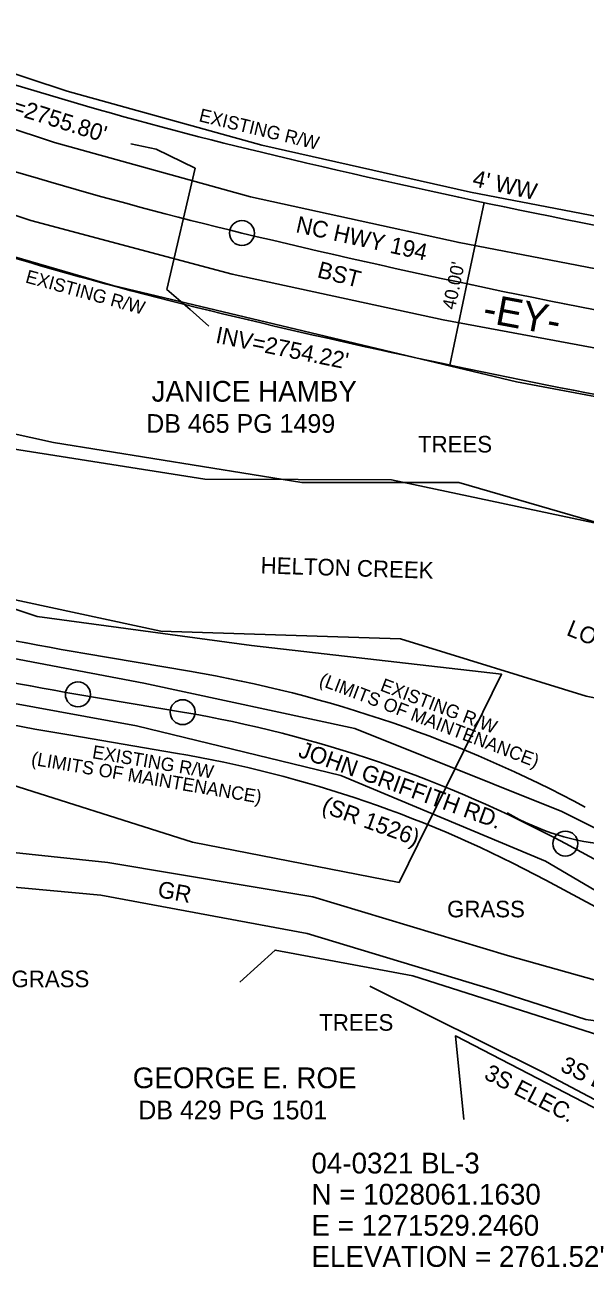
# Model space of a CAD drawing. Extents: x 1271070 to 1271913, y 1027587 to 1028435.
# Drawn here: x 1271367.8 to 1271502.6, y 1028008.8 to 1028308 of the extents above; entities that cross this region are included whole.
import ezdxf

# ---------------------------------------------------------------- set-up
doc = ezdxf.new("R2010")
doc.units = 0
for name, color, linetype in [('CTL Secondary Horizontal and Vertical Text', 7, 'Continuous'), ('Exist Horizontal Alignment', 7, 'Continuous'), ('Exist Horizontal Alignment Direction Label', 7, 'Continuous'), ('Exist Horizontal Alignment Point', 7, 'Continuous'), ('Exist Hydro Jurisdictional Stream or Body of Water', 7, 'Continuous'), ('Exist Hydro Jurisdictional Stream or Body of Water Text', 7, 'Continuous'), ('Exist Other Culture Fence Line', 7, 'Continuous'), ('Exist Other Culture Fence Line Text', 7, 'Continuous'), ('Exist Property Deed Book Text', 7, 'Continuous'), ('Exist Property Owner Text', 7, 'Continuous'), ('Exist Right of Way Line', 7, 'Continuous'), ('Exist Right of Way Line Text', 7, 'Continuous'), ('Exist Right of Way Width CELL', 7, 'Continuous'), ('Exist Roads EOP', 7, 'Continuous'), ('Exist Roads EOP Text', 7, 'Continuous'), ('Exist Roads Soil', 7, 'Continuous'), ('Exist Roads Soil Text', 7, 'Continuous'), ('Exist Structure Minor Pipes CMP 18 Inch', 7, 'Continuous'), ('Exist Structure Minor Pipes CMP 18 Inch Invert', 7, 'Continuous'), ('Exist Structure Minor Pipes CMP 18 Inch Leader', 7, 'Continuous'), ('Exist Utilities Other Located Object Text', 7, 'Continuous'), ('Exist Vegetation Woods Line', 7, 'Continuous'), ('Exist Vegetation Woods Line Text', 7, 'Continuous'), ('Prop Horizontal Alignment', 7, 'Continuous')]:
    doc.layers.add(name, color=color, linetype=linetype)

msp = doc.modelspace()

# ---------------------------------------------------------------- linework, layer by layer
at = {"layer": 'Exist Horizontal Alignment'}
for p, q in [((1271380.54, 1028146.75), (1271405.74, 1028142.48)), ((1271497.89, 1028110.8), (1271529.56, 1028093.74))]:
    msp.add_line(p, q, dxfattribs=at)
for centre, radius, start, end in [((1271654.06, 1029230.12), 1000, 250.65216, 256.46543), ((1271888.09, 1030202.35), 2000, 256.46543, 263.40535), ((1271520.23, 1028970.58), 835.59, 254.00259, 260.37659), ((1271355.59, 1027846.7), 300, 61.6832, 80.3766)]:
    msp.add_arc(centre, radius, start, end, dxfattribs=at)
at = {"layer": 'Exist Horizontal Alignment Point'}
for centre in [(1271420.03, 1028257.89), (1271380.54, 1028146.75), (1271405.74, 1028142.47), (1271497.89, 1028110.8)]:
    msp.add_circle(centre, 3, dxfattribs=at)
at = {"layer": 'Exist Hydro Jurisdictional Stream or Body of Water'}
for points in [[(1271304.7, 1028214.03), (1271358.66, 1028206.9), (1271411.07, 1028198.58), (1271456, 1028198.43), (1271510.08, 1028186.94), (1271560.93, 1028171.69), (1271591.08, 1028158.12), (1271592.88, 1028151.16), (1271591.46, 1028148.01), (1271611.09, 1028139.56), (1271653.5, 1028127.81), (1271692.8, 1028106.61), (1271731.61, 1028109.95), (1271774.25, 1028123.55), (1271810.26, 1028145.38)], [(1271297.21, 1028193.87), (1271353.83, 1028172.03), (1271400.51, 1028161.95), (1271458.18, 1028160.15), (1271502.92, 1028146.33), (1271550.98, 1028136.88), (1271578, 1028118.14), (1271596.52, 1028108.85), (1271635.13, 1028092.8), (1271673.17, 1028073.83), (1271694.14, 1028069.18), (1271732.54, 1028081.77), (1271795.86, 1028101.38), (1271818.57, 1028109)]]:
    msp.add_lwpolyline(points, dxfattribs=at)
at = {"layer": 'Exist Other Culture Fence Line'}
for points in [[(1271329.58, 1028308.04), (1271377.99, 1028292.04), (1271424.8, 1028279.04), (1271475.06, 1028267.76), (1271522.2, 1028258.62), (1271572.4, 1028250.75), (1271617.37, 1028243.97), (1271662.13, 1028238.98), (1271711.39, 1028235.36)], [(1271580.99, 1028013.16), (1271535.55, 1028032.92), (1271492.32, 1028055.79), (1271450.78, 1028076.46)], [(1271473.41, 1028044.33), (1271471.4, 1028064.49), (1271508.77, 1028045.12)]]:
    msp.add_lwpolyline(points, dxfattribs=at)
at = {"layer": 'Exist Right of Way Line'}
for p, q in [((1271382.21, 1028156.61), (1271407.41, 1028152.33)), ((1271378.87, 1028136.89), (1271404.07, 1028132.62)), ((1271493.15, 1028101.99), (1271524.81, 1028084.93))]:
    msp.add_line(p, q, dxfattribs=at)
for centre, radius, start, end in [((1271654.06, 1029230.12), 980, 250.65216, 256.46543), ((1271888.09, 1030202.35), 1980, 256.46543, 263.40535), ((1271654.06, 1029230.12), 1020, 250.65216, 256.46543), ((1271888.09, 1030202.35), 2020, 256.46543, 262.27844), ((1271520.23, 1028970.58), 825.59, 254.00259, 260.37659), ((1271520.23, 1028970.58), 845.59, 254.00259, 260.37659), ((1271355.59, 1027846.7), 310, 61.6832, 80.3766), ((1271355.59, 1027846.7), 290, 61.6832, 80.3766)]:
    msp.add_arc(centre, radius, start, end, dxfattribs=at)
at = {"layer": 'Exist Right of Way Width CELL'}
for p in [(1271478.35, 1028265.21), (1271470.07, 1028226.08)]:
    msp.add_line(p, (1271474.27, 1028245.94), dxfattribs=at)
at = {"layer": 'Exist Roads EOP'}
for points in [[(1271326.12, 1028295.81), (1271374.93, 1028279.7), (1271422.05, 1028266.63), (1271472.3, 1028255.59), (1271520.64, 1028246.3), (1271571.03, 1028237.98), (1271615.64, 1028231.31), (1271659.72, 1028225.08), (1271708.96, 1028218.32), (1271759.42, 1028212.65), (1271812.87, 1028207.39)], [(1271319.45, 1028277.54), (1271369.22, 1028260.92), (1271417.71, 1028247.94), (1271468.48, 1028236.99), (1271517.72, 1028227.81), (1271568.11, 1028219.26), (1271595.03, 1028215.07), (1271602.11, 1028209.33), (1271606.99, 1028200.81), (1271609.21, 1028190.89), (1271609.19, 1028179.92), (1271606.63, 1028171.4)]]:
    msp.add_lwpolyline(points, dxfattribs=at)
at = {"layer": 'Exist Roads Soil'}
for points in [[(1271396.41, 1028149.48), (1271341.01, 1028159.96), (1271291.55, 1028172.76)], [(1271394.68, 1028139.2), (1271338.88, 1028149.38), (1271288.34, 1028161.93)], [(1271396.41, 1028149.48), (1271447.23, 1028138.55), (1271497.02, 1028118.54), (1271535.05, 1028099.55), (1271555.95, 1028097.65), (1271566.94, 1028100.69), (1271573.74, 1028107.16)], [(1271394.68, 1028139.2), (1271443.87, 1028127.22), (1271493.11, 1028106.58), (1271527.33, 1028086.39), (1271534.7, 1028082.23), (1271537.12, 1028081.26), (1271536.99, 1028079.81), (1271526.58, 1028076.45), (1271505.38, 1028077.81), (1271483.98, 1028083.87), (1271437.08, 1028098.01), (1271387.72, 1028106.24)], [(1271387.72, 1028106.24), (1271329.37, 1028112.44), (1271279.97, 1028120.41)], [(1271386.06, 1028098.42), (1271348.48, 1028101.85), (1271337.38, 1028100.86), (1271330.35, 1028097.09), (1271326.29, 1028087.54), (1271323.35, 1028072.9)], [(1271553.57, 1028074.4), (1271542.71, 1028067.79), (1271526.6, 1028065.24), (1271502.81, 1028068.41), (1271480.79, 1028075.51), (1271435.71, 1028089.18), (1271386.06, 1028098.42)]]:
    msp.add_lwpolyline(points, dxfattribs=at)
at = {"layer": 'Exist Structure Minor Pipes CMP 18 Inch'}
msp.add_line((1271408.81, 1028273.54), (1271401.92, 1028244.28), dxfattribs=at)
at = {"layer": 'Exist Structure Minor Pipes CMP 18 Inch Leader'}
for points in [[(1271408.81, 1028273.54), (1271399.42, 1028278.05), (1271393.27, 1028279.41)], [(1271401.92, 1028244.28), (1271407.6, 1028239.46), (1271412.07, 1028235.46)]]:
    msp.add_lwpolyline(points, dxfattribs=at)
at = {"layer": 'Exist Vegetation Woods Line'}
for points in [[(1271320.34, 1028265.26), (1271388.96, 1028245.21), (1271486.11, 1028222.06), (1271555.88, 1028208.95), (1271583.64, 1028180.02), (1271579.16, 1028169.47), (1271530.83, 1028180.79), (1271472.23, 1028197.76), (1271434.45, 1028197.76), (1271374.7, 1028207.41), (1271327.66, 1028217.82), (1271304.15, 1028229.39)], [(1271299.01, 1028189.41), (1271370.71, 1028165.49), (1271422.37, 1028158.55), (1271482.51, 1028151.61), (1271457.84, 1028101.47), (1271408.11, 1028111.11), (1271359.53, 1028126.54), (1271286.29, 1028135.41)], [(1271419.54, 1028077.42), (1271428.02, 1028085.14), (1271461.18, 1028078.97), (1271511.68, 1028062.77), (1271549.84, 1028032.3), (1271603.43, 1028018.41), (1271647.71, 1028044.28), (1271672.05, 1028067.4), (1271748.76, 1028084.37), (1271798.88, 1028091.69)]]:
    msp.add_lwpolyline(points, dxfattribs=at)
at = {"layer": 'Prop Horizontal Alignment'}
msp.add_arc((1271513.72, 1028170.23), 60, 240.1367, 340.6957, dxfattribs=at)

# ---------------------------------------------------------------- texts
at = {"layer": 'CTL Secondary Horizontal and Vertical Text'}
for s, p in [('04-0321 BL-3', (1271436.75, 1028031.34)), ('N = 1028061.1630', (1271436.75, 1028023.84)), ('E = 1271529.2460', (1271436.75, 1028016.34)), ("ELEVATION = 2761.52'", (1271436.75, 1028008.84))]:
    msp.add_text(s, height=5, dxfattribs=at).set_placement(p)
at = {"layer": 'Exist Horizontal Alignment Direction Label'}
msp.add_text('-EY-', height=7, rotation=349.4688, dxfattribs=at).set_placement((1271477.7, 1028236.51))
at = {"layer": 'Exist Hydro Jurisdictional Stream or Body of Water Text'}
msp.add_text('HELTON CREEK', height=4, rotation=358.2194, dxfattribs=at).set_placement((1271424.48, 1028175.89))
at = {"layer": 'Exist Other Culture Fence Line Text'}
for s, rotation, p in [("4' WW", 347.3523, (1271475.31, 1028269.25)), ('3S ELEC.', 332.6028, (1271478.05, 1028054.29)), ('3S BW', 334.3271, (1271496.41, 1028056.14))]:
    msp.add_text(s, height=4, rotation=rotation, dxfattribs=at).set_placement(p)
at = {"layer": 'Exist Property Deed Book Text'}
for s, p in [('DB 465 PG 1499', (1271396.98, 1028209.76)), ('DB 429 PG 1501', (1271395.08, 1028044.38))]:
    msp.add_text(s, height=4.5, dxfattribs=at).set_placement(p)
at = {"layer": 'Exist Property Owner Text'}
for s, p in [('JANICE HAMBY', (1271398.29, 1028217.26)), ('GEORGE E. ROE', (1271393.75, 1028051.88))]:
    msp.add_text(s, height=5, dxfattribs=at).set_placement(p)
at = {"layer": 'Exist Right of Way Line Text'}
for s, rotation, p in [('EXISTING R/W', 346.4654, (1271409.49, 1028284.83)), ('EXISTING R/W', 344.6657, (1271367.72, 1028246.01)), ('(LIMITS OF MAINTENANCE)', 339.1166, (1271438.39, 1028149.05)), ('EXISTING R/W', 339.1166, (1271453.1, 1028147.73)), ('EXISTING R/W', 350.3766, (1271383.84, 1028131.39)), ('(LIMITS OF MAINTENANCE)', 350.3766, (1271369.16, 1028129.82))]:
    msp.add_text(s, height=3.2, rotation=rotation, dxfattribs=at).set_placement(p)
at = {"layer": 'Exist Right of Way Width CELL'}
msp.add_text("40.00'", height=3.2, rotation=78.0569, dxfattribs=at).set_placement((1271471.3, 1028239.26))
at = {"layer": 'Exist Roads EOP Text'}
for s, rotation, p in [('NC HWY 194', 347.6033, (1271432.79, 1028258.13)), ('BST', 345.7388, (1271437.94, 1028247.27))]:
    msp.add_text(s, height=4, rotation=rotation, dxfattribs=at).set_placement(p)
at = {"layer": 'Exist Roads Soil Text'}
for s, rotation, p in [('JOHN GRIFFITH RD.', 340.0379, (1271433.34, 1028131.8)), ('(SR 1526)', 340.0379, (1271438.97, 1028118.47)), ('GR', 349.4497, (1271399.54, 1028097.95))]:
    msp.add_text(s, height=4, rotation=rotation, dxfattribs=at).set_placement(p)
at = {"layer": 'Exist Structure Minor Pipes CMP 18 Inch Invert'}
for s, rotation, p in [("INV=2755.80'", 342.4667, (1271355.84, 1028289.44)), ("INV=2754.22'", 348.5252, (1271413.48, 1028231.48))]:
    msp.add_text(s, height=4, rotation=rotation, dxfattribs=at).set_placement(p)
at = {"layer": 'Exist Utilities Other Located Object Text'}
msp.add_text("LOW WIRE=2785.96'", height=4, rotation=337.9808, dxfattribs=at).set_placement((1271497.9, 1028161.11))
at = {"layer": 'Exist Vegetation Woods Line Text'}
for s, p in [('TREES', (1271462.41, 1028205.02)), ('GRASS', (1271469.41, 1028093.04)), ('GRASS', (1271364.57, 1028076.21)), ('TREES', (1271438.64, 1028065.72))]:
    msp.add_text(s, height=4, dxfattribs=at).set_placement(p)

doc.saveas('drawing.dxf')
